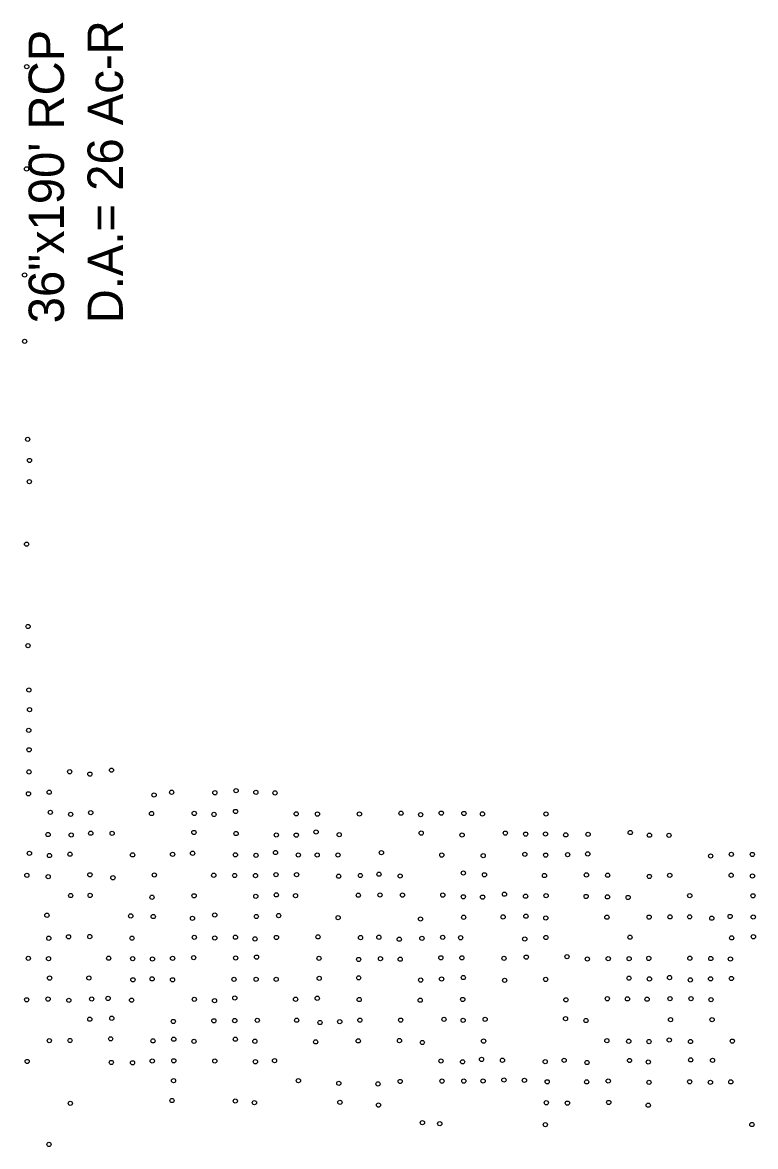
# Model space of a CAD drawing. Extents: x 20503438 to 20508873, y 7964251 to 7984667.
# Drawn here: x 20505711 to 20506059, y 7978794 to 7979329 of the extents above; entities that cross this region are included whole.
import ezdxf

# ---------------------------------------------------------------- set-up
doc = ezdxf.new("R2010")
doc.units = 0
doc.layers.add('SurSurveyPoints', color=7, linetype='Continuous')
doc.layers.add('SurTxtDrainage', color=7, linetype='Continuous')

msp = doc.modelspace()

# ---------------------------------------------------------------- linework, layer by layer
at = {"layer": 'SurSurveyPoints'}
for centre in [(20505712.7, 7979307.86), (20505712.6, 7979259.22), (20505711.67, 7979208.75), (20505711.7, 7979177.2), (20505713.14, 7979130.51), (20505714, 7979120.48), (20505713.93, 7979110.37), (20505712.61, 7979080.65), (20505713.32, 7979041.46), (20505713.31, 7979032.34), (20505713.71, 7979011.27), (20505714.01, 7979001.89), (20505713.65, 7978992.06), (20505713.8, 7978982.79), (20505753, 7978973.09), (20505713.75, 7978972.26), (20505733.12, 7978972.34), (20505742.71, 7978971.2), (20505723.37, 7978962.6), (20505781.6, 7978962.59), (20505802.17, 7978962.35), (20505812.25, 7978963.31), (20505821.65, 7978962.53), (20505830.75, 7978962.27), (20505713.5, 7978961.84), (20505773.25, 7978961.29), (20505723.93, 7978953.01), (20505733.56, 7978952.09), (20505743.13, 7978952.87), (20505772.04, 7978952.46), (20505792.35, 7978952.52), (20505801.73, 7978952.03), (20505812.02, 7978953.43), (20505840.85, 7978952.31), (20505850.95, 7978952.2), (20505870.91, 7978952.21), (20505890.67, 7978952.62), (20505900.01, 7978951.93), (20505909.83, 7978952.65), (20505920.61, 7978952.48), (20505929.42, 7978952.27), (20505959.65, 7978952.24), (20505722.84, 7978942.46), (20505733.83, 7978942.26), (20505743.14, 7978943.1), (20505753.3, 7978943.02), (20505792.19, 7978943.44), (20505812.25, 7978942.94), (20505831.39, 7978942.26), (20505840.87, 7978942.19), (20505850.3, 7978943.67), (20505861.29, 7978942.4), (20505900.29, 7978943.15), (20505919.73, 7978942.22), (20505940.28, 7978943.13), (20505949.97, 7978942.65), (20505959.41, 7978942.71), (20505969.04, 7978942.31), (20505979.65, 7978942.57), (20505999.71, 7978943.41), (20506008.83, 7978942.14), (20506018.14, 7978942.08), (20505713.97, 7978933.5), (20505723.49, 7978932.47), (20505733.27, 7978933.09), (20505763.02, 7978932.78), (20505782.05, 7978933.04), (20505791.57, 7978933.56), (20505811.93, 7978932.8), (20505821.74, 7978932.58), (20505830.99, 7978933.9), (20505841.84, 7978932.73), (20505850.83, 7978932.71), (20505860.73, 7978932.7), (20505881.36, 7978933.82), (20505910.08, 7978932.69), (20505929.77, 7978932.39), (20505949.58, 7978933.06), (20505959.5, 7978932.66), (20505969.94, 7978932.89), (20505979.49, 7978933.23), (20506037.93, 7978932.25), (20506047.79, 7978933.02), (20506057.75, 7978932.99), (20505712.76, 7978923.02), (20505722.89, 7978922.4), (20505742.74, 7978923.3), (20505753.68, 7978921.9), (20505773.38, 7978923.22), (20505801.62, 7978923.09), (20505811.6, 7978922.96), (20505821.49, 7978922.93), (20505831.25, 7978923.37), (20505841.02, 7978923.35), (20505861.06, 7978922.64), (20505871.33, 7978922.96), (20505880.21, 7978923.58), (20505890.28, 7978922.75), (20505920.35, 7978924.15), (20505930.38, 7978923.31), (20505958.92, 7978922.94), (20505978.87, 7978923.24), (20505988.98, 7978923.1), (20506008.76, 7978922.51), (20506018.5, 7978923.03), (20506047.71, 7978923.08), (20506057.84, 7978922.7), (20505939.88, 7978914.06), (20505733.56, 7978913.42), (20505742.84, 7978913.49), (20505772.26, 7978912.62), (20505792.27, 7978913.31), (20505821.63, 7978913.07), (20505831.4, 7978913.74), (20505840.52, 7978913.35), (20505870.41, 7978913.59), (20505880.67, 7978913.69), (20505891.4, 7978913.64), (20505910.57, 7978913.64), (20505920.34, 7978912.84), (20505929.49, 7978912.68), (20505949.93, 7978913.12), (20505959.68, 7978913.38), (20505978.72, 7978912.99), (20505988.87, 7978912.79), (20505998.69, 7978912.51), (20506028.01, 7978913.35), (20506058.11, 7978913.32), (20505722.29, 7978904.05), (20505762.16, 7978903.73), (20505772.85, 7978903.43), (20505802.11, 7978904.14), (20505821.87, 7978903.45), (20505832.49, 7978903.89), (20505950.09, 7978903.6), (20506047.2, 7978903.47), (20505791.51, 7978902.56), (20505860.79, 7978902.9), (20505899.96, 7978902.29), (20505920.46, 7978903.09), (20505939.25, 7978903.26), (20505959.54, 7978902.75), (20505988.62, 7978903.12), (20506008.69, 7978903.16), (20506018.61, 7978903.28), (20506027.97, 7978903.29), (20506038.48, 7978902.64), (20506058.2, 7978903.19), (20505723.17, 7978893.1), (20505732.58, 7978893.79), (20505742.67, 7978893.89), (20505762.72, 7978893.14), (20505792.38, 7978893.55), (20505802.1, 7978893.24), (20505811.95, 7978893.6), (20505821.25, 7978892.78), (20505831.43, 7978893.49), (20505851.21, 7978893.76), (20505871.43, 7978893.42), (20505880.15, 7978893.58), (20505900.63, 7978893.06), (20505910.52, 7978893.56), (20505919.05, 7978893.35), (20505949.53, 7978892.74), (20505959.61, 7978893.46), (20505999.58, 7978893.59), (20506047.92, 7978893.28), (20506058.28, 7978893.82), (20505889.85, 7978892.64), (20505713.43, 7978883.57), (20505723.06, 7978883.39), (20505751.63, 7978883.61), (20505763.07, 7978883.37), (20505772.48, 7978883.22), (20505782.05, 7978883.56), (20505792.08, 7978883.84), (20505812.03, 7978883.72), (20505821.99, 7978884.12), (20505851.71, 7978883.54), (20505870.57, 7978883.01), (20505880.92, 7978883.41), (20505890.31, 7978883.12), (20505909.65, 7978883.8), (20505919.63, 7978883.79), (20505939.65, 7978883.57), (20505950.25, 7978884.12), (20505969.64, 7978884.31), (20505979.32, 7978883.2), (20505989.25, 7978883.41), (20505999.17, 7978883.41), (20506008.53, 7978883.5), (20506028.05, 7978883.58), (20506038.02, 7978883.44), (20506047.35, 7978883.24), (20505723.56, 7978874.15), (20505742.24, 7978874.18), (20505763.19, 7978873.34), (20505772.33, 7978873.78), (20505782.02, 7978873.33), (20505811.26, 7978873.55), (20505821.79, 7978873.58), (20505831.32, 7978873.56), (20505851.78, 7978874.03), (20505870.52, 7978874.27), (20505900.05, 7978873.19), (20505909.99, 7978873.69), (20505920.33, 7978874.4), (20505939.96, 7978873.1), (20505959.5, 7978873.52), (20505999.12, 7978874.11), (20506008.83, 7978873.75), (20506018.39, 7978874.38), (20506028.26, 7978873.28), (20506037.92, 7978873.79), (20506047.83, 7978873.95), (20505712.66, 7978863.81), (20505722.83, 7978864.15), (20505732.71, 7978863.56), (20505743.58, 7978864.19), (20505751.38, 7978864.47), (20505762.56, 7978863.64), (20505792.38, 7978864.05), (20505802.01, 7978863.42), (20505811.63, 7978864.66), (20505840.55, 7978864.08), (20505850.86, 7978864.55), (20505870.81, 7978863.93), (20505899.82, 7978863.62), (20505920.04, 7978863.97), (20505969.12, 7978863.79), (20505988.84, 7978864.31), (20505998.38, 7978864.25), (20506007.71, 7978864.1), (20506018.61, 7978864.33), (20506028.59, 7978864.36), (20506038.13, 7978863.9), (20505742.67, 7978854.58), (20505753.15, 7978855.03), (20505782.38, 7978853.5), (20505801.68, 7978853.83), (20505811.62, 7978853.93), (20505822.35, 7978854.07), (20505841.07, 7978854.09), (20505852.13, 7978852.98), (20505861.55, 7978853.39), (20505871.13, 7978854.12), (20505890.51, 7978854.13), (20505911.13, 7978854.53), (20505920.23, 7978854.04), (20505930.7, 7978854.53), (20505968.93, 7978854.85), (20505978.67, 7978853.94), (20506018.86, 7978854.38), (20506038.62, 7978854.33), (20505752.61, 7978845.24), (20505782.6, 7978845.05), (20505811.91, 7978845.06), (20506018.26, 7978844.68), (20505723.43, 7978844.38), (20505733.28, 7978844.44), (20505772.72, 7978844.26), (20505792.26, 7978844.07), (20505821.18, 7978844.08), (20505850.08, 7978843.78), (20505870.35, 7978844.26), (20505889.94, 7978844.41), (20505900.85, 7978843.49), (20505929.95, 7978844.16), (20505988.59, 7978844.37), (20505998.99, 7978844.09), (20506008.65, 7978843.92), (20506028.37, 7978843.94), (20506048.25, 7978844.15), (20505712.89, 7978834.47), (20505752.9, 7978834), (20505763, 7978833.83), (20505772.38, 7978834.69), (20505782.63, 7978834.79), (20505802.12, 7978834.71), (20505821.44, 7978834.33), (20505830.54, 7978834.84), (20505909.71, 7978834.71), (20505919.97, 7978834.29), (20505928.99, 7978835.45), (20505938.93, 7978835.05), (20505959.26, 7978834.38), (20505968.28, 7978835.01), (20505979.13, 7978833.96), (20505999.36, 7978834.92), (20506008.3, 7978834.2), (20506028.43, 7978835.23), (20506038.84, 7978835.03), (20505782.51, 7978825.34), (20505841.89, 7978825.33), (20505861.11, 7978824.08), (20505879.77, 7978823.79), (20505890.28, 7978824.94), (20505910.21, 7978825.13), (20505920.54, 7978825.13), (20505929.72, 7978825.17), (20505939.62, 7978825.63), (20505949.37, 7978825.5), (20505960.22, 7978824.78), (20505978.98, 7978824.76), (20505989.25, 7978825.16), (20506008.62, 7978824.55), (20506027.96, 7978824.8), (20506037.84, 7978824.51), (20506047.52, 7978824.75), (20505733.4, 7978814.54), (20505781.76, 7978815.86), (20505811.87, 7978815.63), (20505820.96, 7978814.83), (20505861.64, 7978815.02), (20505879.98, 7978813.7), (20505959.79, 7978814.82), (20505969.82, 7978814.65), (20505989.49, 7978814.96), (20506008.28, 7978813.64), (20505900.86, 7978805.32), (20505909.11, 7978804.84), (20505959.33, 7978804.41), (20506057.57, 7978804.45), (20505723.27, 7978794.99)]:
    msp.add_circle(centre, 1, dxfattribs=at)

# ---------------------------------------------------------------- texts
at = {"layer": 'SurTxtDrainage'}
for s, p in [('D.A.= 26 Ac-R', (20505758.4, 7979185.75)), ('36"x190\' RCP', (20505730.4, 7979185.75))]:
    msp.add_text(s, height=16.8, rotation=90, dxfattribs=at).set_placement(p)

doc.saveas('drawing.dxf')
